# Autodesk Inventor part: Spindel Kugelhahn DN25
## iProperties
Shininess: 64.0
Length Units: 11269
Angle Units: 11279
Time Units: 11290
Mass Units: 11283
Length Display Precision: 3
Angle Display Precision: 2
Compacted: True
Part Number: Spindel Kugelhahn DN25
Document SubType Name: Modeling
Created: 2003-12
Material: Messing (weiches, gelbes Messing)
Description: Spindel für Kugelhahn
Designer: AG
Manufacturer: Standard
Standards Organization: Custom
Density: 0.0
Volumn: 0.0
Area: 0.0
PropertySet Name: Model Information
Control State: 0
Master: False
Checked Out: False
Author: AG
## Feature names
1. Extrusion1
2. Extrusion2
3. Extrusion3
4. Bohrung1 [Hole]
5. Extrusion4
6. Extrusion5
